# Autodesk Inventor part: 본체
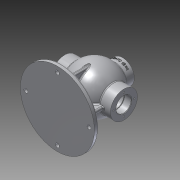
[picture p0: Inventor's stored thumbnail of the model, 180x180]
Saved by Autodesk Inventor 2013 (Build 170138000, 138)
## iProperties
Created: 2020-08
Part Number: 본체
Material: 알루미늄 6061
Document SubType Name: Modeling
Designer: 99
Density: 2.71 g/cm^3
Mass: 1779.97 g
Surface Area: 1358.86 cm^2
Volume: 656.815 cm^3
Author: 99
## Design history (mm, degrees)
sketch "스케치1"
  geometry: L1 (-42.988, 31)-(-68, 31); L2 (42.988, 31)-(68, 31); L3 (-68, 0)-(68, 0); L4 (0, 53)-(0, -53); L5 (-68, 31)-(-68, 17.5); L6 (68, 31)-(68, 17.5); L7 (-68, 17.5)-(-52, 17.5); L8 (-52, 17.5)-(-39.278, 17.5); L9 (52, 18.5)-(50.25, 18.5); L10 (52, 17.5)-(52, 18.5); L11 (50.25, 18.5)-(50.25, 17.5); L12 (39.278, 17.5)-(50.25, 17.5); L13 (52, 17.5)-(68, 17.5); A1 r 43 centre (0, 0) between (39.278, 17.5) and (-39.278, 17.5); A2 r 53 centre (0, 0) between (42.988, 31) and (-42.988, 31); 5 further points
  constraints: 26 end point, 5 collinear, 5 perpendicular, 4 coincident, 4 point on circle, 3 midpoint, 2 centre point, 2 horizontal, 1 horizontal alignment, 1 symmetric about line, 1 other
  dimensions: "d9" = 43 radius of A1; "d12" = 136 distance between parallel lines of L6 L5; "d19" = 53 radius of A2; "d20" = 62 diameter of L1 L3; "d21" = 35 diameter of L7 L3; "d88" = 1.75 distance of L9.start L9.end; "d89" = 37 diameter of L9 L3; "d90" = 16 distance between parallel lines of L6 L10
revolve "회전1" sketch "스케치1" stored, may be unused: angle "d23" = 90 deg
node "작업 평면1"
sketch "스케치2"
  geometry: C1 r 27 at (0, 0); 1 further point
  constraints: 1 centre point, 1 coincident
  dimensions: "d25" = 54 diameter of C1
extrude "돌출1" join sketch "스케치2" stored distance "d26" = 10; taper "d27" = 0 deg
sketch "스케치3"
  geometry: C1 r 27 at (0, 0) reference
hole "구멍1" diameter "d30" = 26; stored, may be unused: countersink angle "d34" = 90 deg, drill point angle "d36" = 118 deg; dims "d28" = 10, "d29" = 10, "d31" = 6, "d32" = 4, "d33" = 2, "d35" = 8
sketch "스케치4" dims "d37" = 40
  geometry: C1 r 13 at (0, 0) reference; C2 r 27 at (0, 0) reference; 2 further points
  constraints: 2 vertical alignment, 1 coincident, 2 other
hole "구멍2" sketch "스케치4" at (0, 20) diameter "d38" = 3.242; stored, may be unused: countersink angle "d42" = 82 deg, drill point angle "d44" = 118 deg; dims "d39" = 12, "d40" = 3.023, "d41" = 2, "d43" = 15
sketch "스케치5" dims "d48" = 48
  geometry: C1 r 17.5 at (0, 0) reference; C2 r 31 at (0, 0) reference; 2 further points
  constraints: 3 coincident, 2 vertical alignment, 2 other
hole "구멍3" sketch "스케치5" at (0, 24) diameter "d49" = 3.242; stored, may be unused: countersink angle "d53" = 82 deg, drill point angle "d55" = 118 deg; dims "d50" = 12, "d51" = 3.023, "d52" = 2, "d54" = 15
node "작업 평면2"
sketch "스케치6" dims "d60" = 170
  geometry: L1 (-4, 52)-(4, 52); L2 (4, -52)-(-4, -52); L3 (52, 4)-(52, -4); L4 (-52, -4)-(-52, 4); L5 (-52, 4)-(-4, 4); L6 (4, 4)-(52, 4); L7 (52, -4)-(4, -4); L8 (-4, -4)-(-52, -4); L9 (-4, -52)-(-4, -4); L10 (-4, 4)-(-4, 52); L11 (4, 52)-(4, 4); L12 (4, -4)-(4, -52); L13 (0, 52)-(0, -52); L14 (-85, 0)-(-72.5, 0); 5 further points
  constraints: 28 end point, 10 parallel, 5 midpoint, 5 perpendicular, 4 collinear, 3 horizontal, 3 horizontal alignment, 1 coincident, 1 vertical alignment, 4 other
  dimensions: "d62" = 8 distance between parallel lines of L10 L11; "d63" = 8 distance of L3.start L3.end; "d64" = 104 distance from line of L1.end L2; "d65" = 104 distance from line of L3 point (-52, 0)
extrude "돌출2" join sketch "스케치6" distance "d66" = 10; taper "d67" = 0 deg
extrude "돌출3" join sketch "스케치6" stored distance "d68" = 10; taper "d69" = 0 deg
node "작업 평면3"
sketch "스케치7"
  geometry: L1 (27, 65)-(27, 45.607) reference; L2 (-27, 45.607)-(27, 45.607) reference; L3 (-27, 65)-(27, 65) reference; L4 (-27, 65)-(-27, 45.607) reference; L5 (-27, 65)-(-27, 45.607) reference; 2 further points
  constraints: 1 other
  dimensions: "d86" = 27 distance from line of point (0, 56) L4; "d87" = 9 distance from line of point (0, 56) L3
feature "엠보싱1" sketch "스케치7" dims "d71" = 0.5, "d72" = 0
fillet "모깎기1" dims "d73" = 3
sketch "스케치8" dims "d74" = 145
  geometry: C1 r 82 at (0, 0) reference; 2 further points
  constraints: 2 vertical alignment, 1 coincident, 2 other
hole "구멍4" sketch "스케치8" at (0, 72.5) diameter "d76" = 9; stored, may be unused: countersink angle "d80" = 90 deg, drill point angle "d82" = 118 deg; dims "d77" = 6, "d78" = 4, "d79" = 2, "d81" = 8
chamfer "모따기1" distance "d91" = 1; stored, may be unused: second distance "d92" = 2, angle "d93" = 45 deg
node "솔리드1"
pattern_circular "원형 패턴1" dims angle "d46" = 360 deg
pattern_circular "원형 패턴2" dims angle "d57" = 360 deg
mirror "대칭1"
pattern_circular "원형 패턴3" dims angle "d84" = 360 deg
node "투영된 루프1"
other parameters: "d0" = 106, "d1" = 136, "d7" = 136, "d8" = 86, "d16" = 106, "d18" = 53, "d24" = 65, "d70" = 89.5
